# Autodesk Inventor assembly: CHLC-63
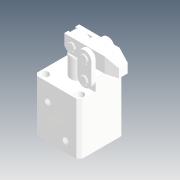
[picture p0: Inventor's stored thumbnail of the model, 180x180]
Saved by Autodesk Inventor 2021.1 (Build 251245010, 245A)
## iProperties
Created: 2019-04
Part Number: CHLC-63
Description: STEP AP214
Document SubType Name: Assembly
Designer: user
Title: CHLC-63.STEP
Revision Number: ÈÎºÎ
Sending System: SolidWorks 2016
Preprocessor: SwSTEP 2.0
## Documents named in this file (8)
- D:\Vault_2016\Projekty\Clamptek\Hydraulic\CHLC\CHLC-63\Inventor\CHLC-63\CHLC-63.iam
- D:\Vault_2016\Projekty\Clamptek\Hydraulic\CHLC\CHLC-63\Inventor\CHLC-63\CHLC-63-06.ipt
- D:\Vault_2016\Projekty\Clamptek\Hydraulic\CHLC\CHLC-63\Inventor\CHLC-63\CHLC-63-05.ipt
- D:\Vault_2016\Projekty\Clamptek\Hydraulic\CHLC\CHLC-63\Inventor\CHLC-63\CHLC-63-01.ipt
- D:\Vault_2016\Projekty\Clamptek\Hydraulic\CHLC\CHLC-63\Inventor\CHLC-63\CHLC-63-04.ipt
- D:\Vault_2016\Projekty\Clamptek\Hydraulic\CHLC\CHLC-63\Inventor\CHLC-63\CHLC-63-02.ipt
- D:\Vault_2016\Projekty\Clamptek\Hydraulic\CHLC\CHLC-63\Inventor\CHLC-63\CHLC-63-03.ipt
- D:\Vault_2016\Projekty\Clamptek\Hydraulic\CHLC\CHLC-63\Inventor\CHLC-63\CHLC-63-07.ipt
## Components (14 placed, 14 different names)
1. CHLC-63-06_1
2. CHLC-63-05_2
3. CHLC-63-01_3
4. CHLC-63-04_4
5. CHLC-63-04_5
6. CHLC-63-02_6
7. CHLC-63-03_7
8. CHLC-63-03_8
9. CHLC-63-07_9
10. CHLC-63-07_10
11. CHLC-63-07_11
12. CHLC-63-07_12
13. CHLC-63-07_13
14. CHLC-63-07_14
